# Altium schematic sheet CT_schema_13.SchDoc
size 387 x 278 mm
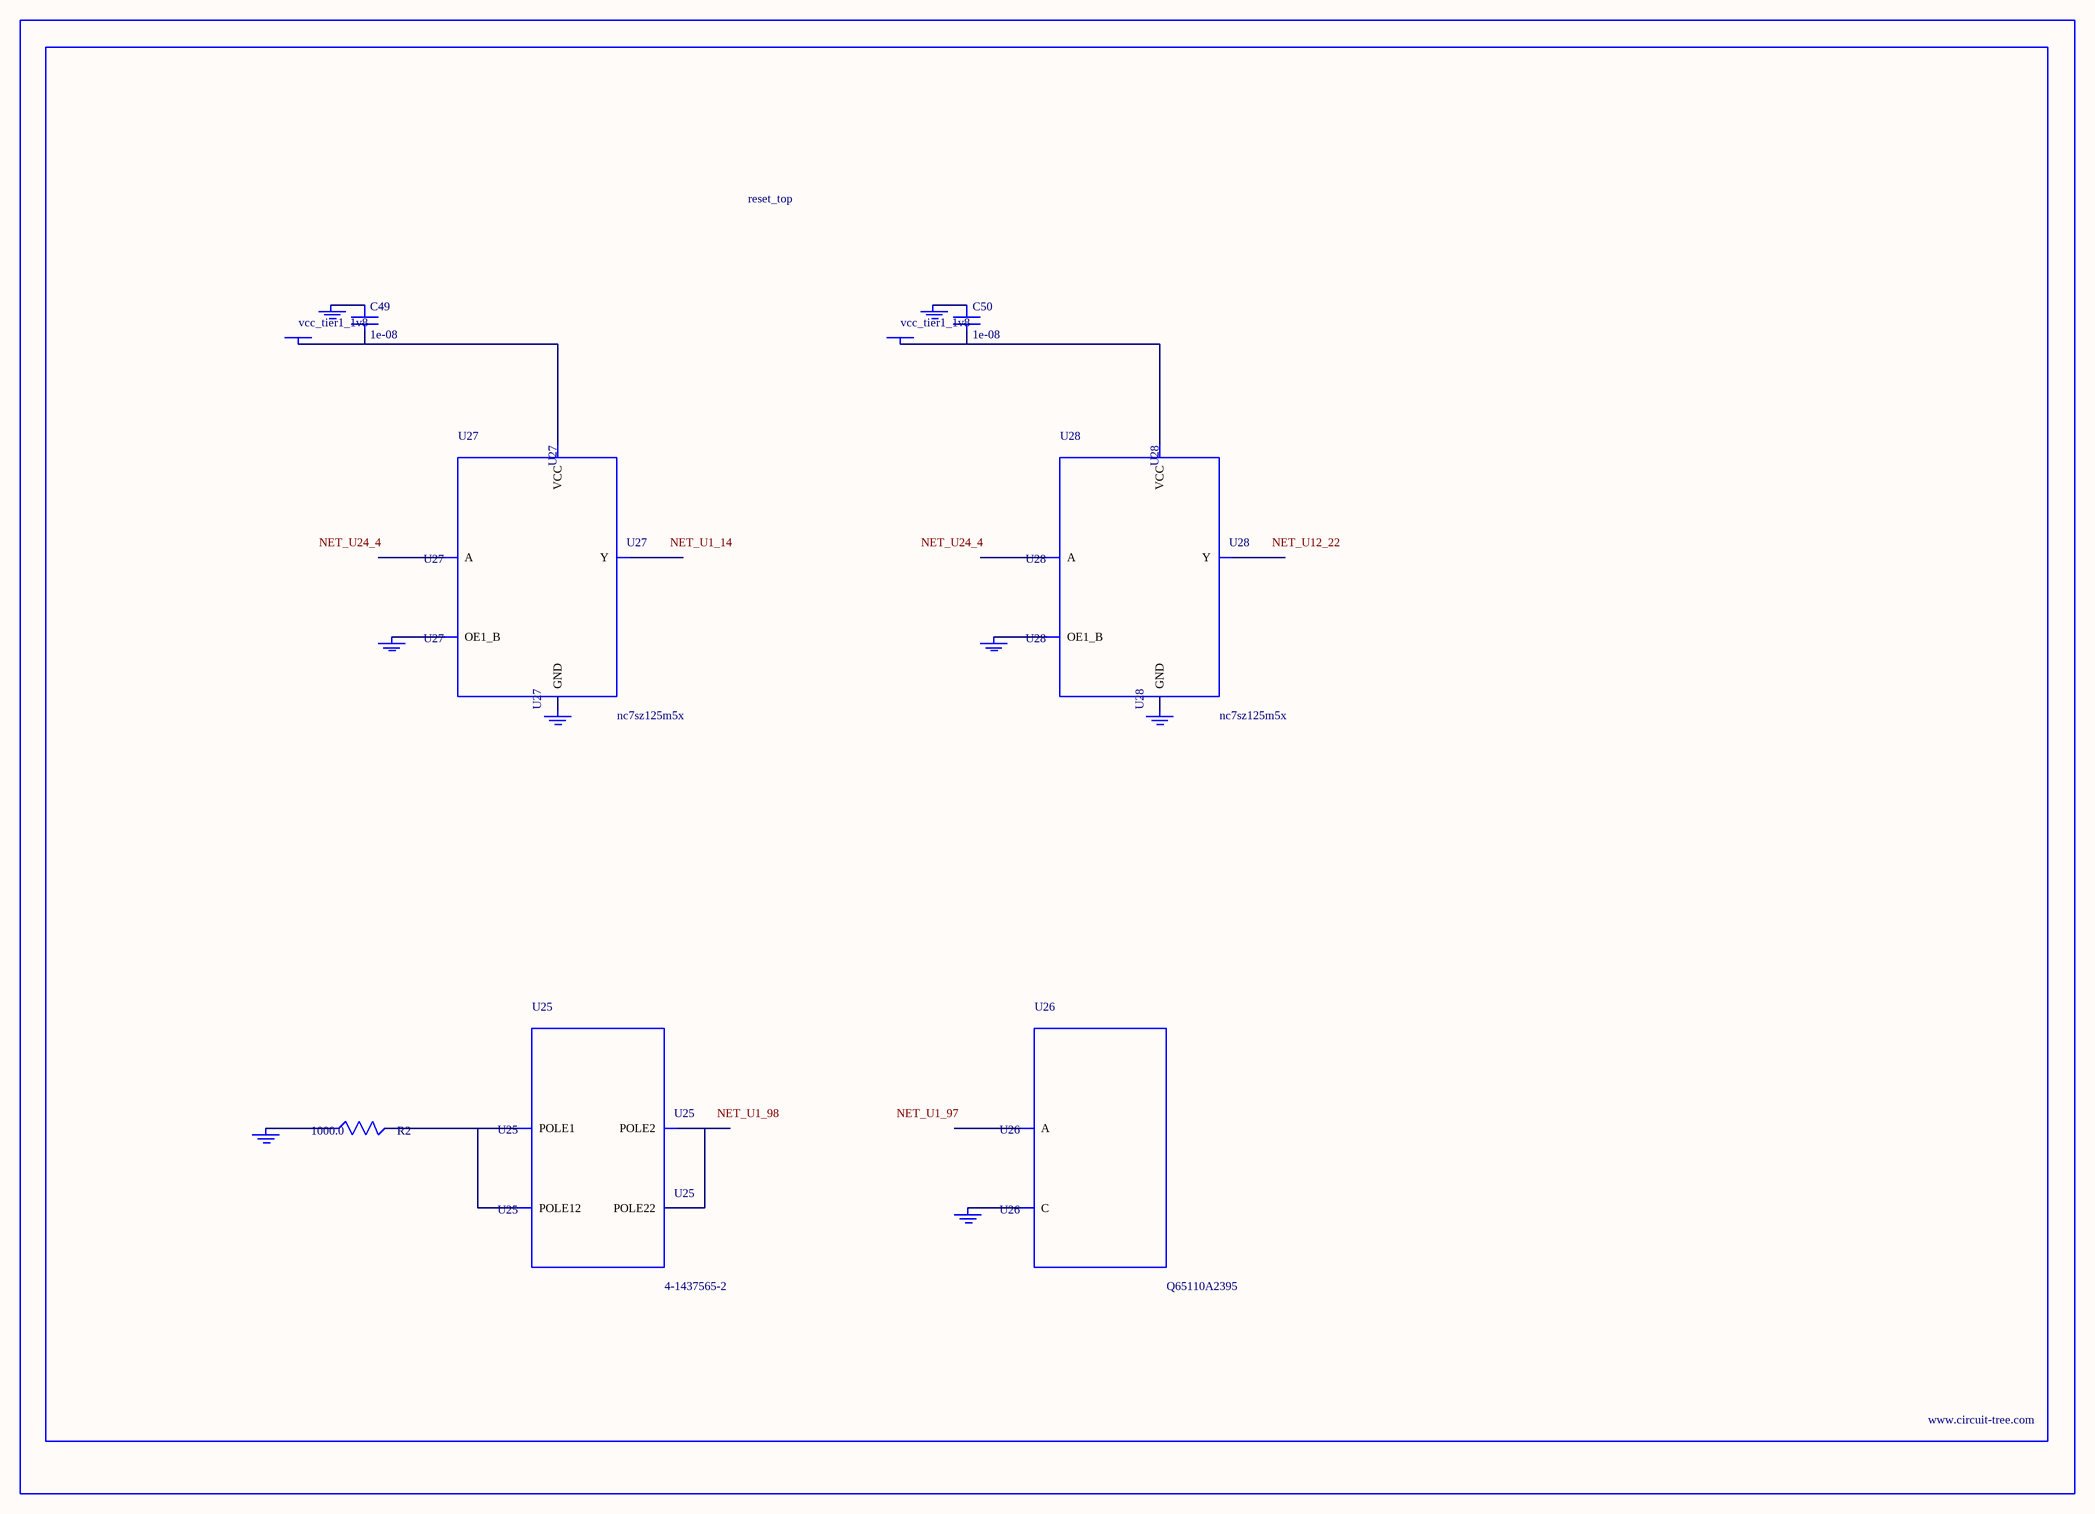
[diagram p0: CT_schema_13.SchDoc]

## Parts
BORDER12  (no value)
C49  1e-08  [C0402]
C50  1e-08  [C0402]
GND_INSTANCE_12_0  (no value)
GND_INSTANCE_12_1  (no value)
GND_INSTANCE_12_2  (no value)
GND_INSTANCE_12_3  (no value)
GND_INSTANCE_12_4  (no value)
GND_INSTANCE_12_5  (no value)
GND_INSTANCE_12_6  (no value)
GND_INSTANCE_12_7  (no value)
POWER_INSTANCE_12_0  vcc_tier1_1v8
POWER_INSTANCE_12_1  vcc_tier1_1v8
R2  1000.0  [R0603]
U25  4-1437565-2  [SW_4-1437565-2]
U26  Q65110A2395  [LGM67K-G1J2-24-Z]
U27  nc7sz125m5x  [NC7SZ125M5X]
U28  nc7sz125m5x  [NC7SZ125M5X]

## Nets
NetC49_1: C49.1 GND_INSTANCE_12_2.0(GND)
NetC49_2: C49.2 POWER_INSTANCE_12_0.0(PWR) U27.5(VCC)
NetC50_1: C50.1 GND_INSTANCE_12_5.0(GND)
NetC50_2: C50.2 POWER_INSTANCE_12_1.0(PWR) U28.5(VCC)
NetGND_INSTANCE_12_0_0: GND_INSTANCE_12_0.0(GND) R2.1
NetGND_INSTANCE_12_1_0: GND_INSTANCE_12_1.0(GND) U26.C
NetGND_INSTANCE_12_3_0: GND_INSTANCE_12_3.0(GND) U27.1(OE1_B)
NetGND_INSTANCE_12_4_0: GND_INSTANCE_12_4.0(GND) U27.3(GND)
NetGND_INSTANCE_12_6_0: GND_INSTANCE_12_6.0(GND) U28.1(OE1_B)
NetGND_INSTANCE_12_7_0: GND_INSTANCE_12_7.0(GND) U28.3(GND)
NetR2_2: R2.2 U25.1(POLE1) U25.2(POLE12)
NetU25_3: U25.3(POLE2) U25.4(POLE22)

Not connected (* = marked no-connect by the designer): U26 A; U27 2(A) 4(Y); U28 2(A) 4(Y)

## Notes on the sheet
- Labels drawn without touching a wire or pin: NET_U1_14, NET_U1_97, NET_U1_98, NET_U12_22, NET_U24_4

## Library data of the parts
BORDER12 = BORDER_PAGE12
C49 C50 = C0402C103K3RAC
GND_INSTANCE_12_0-GND_INSTANCE_12_7 = GND
POWER_INSTANCE_12_0 POWER_INSTANCE_12_1 = PWR
R2 = RC0603JR-071KL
